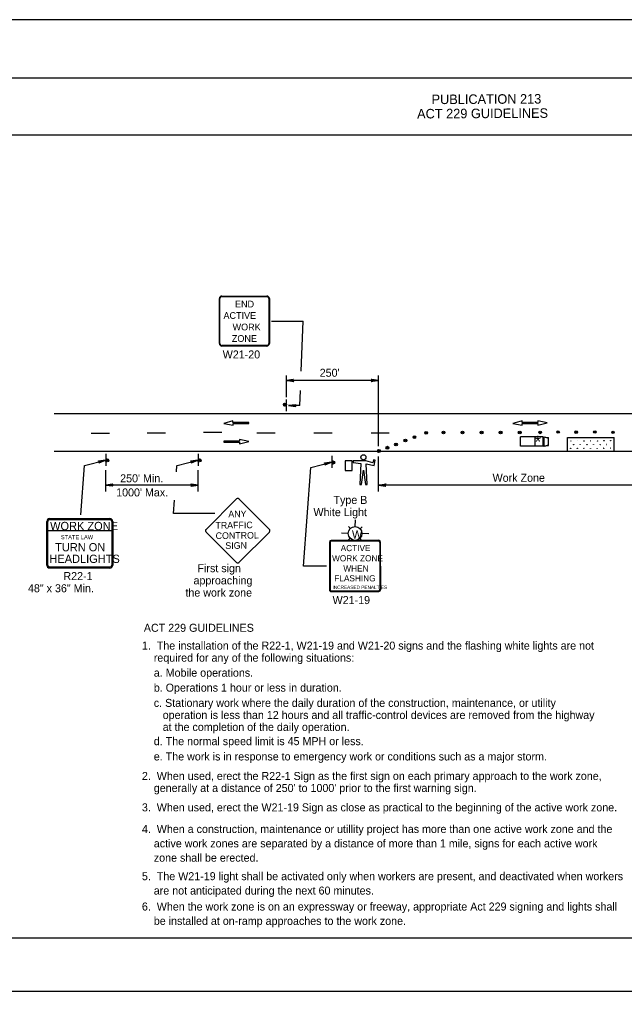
# Model space of a CAD drawing. Extents: x -14145 to -13521, y 30244 to 30661.
# Drawn here: x -13684.79 to -13668.9, y 30559.81 to 30585.31 of the extents above; entities that cross this region are included whole.
import ezdxf

# ---------------------------------------------------------------- set-up
doc = ezdxf.new("R2010")
doc.units = 0
for name, color, linetype in [('1', 7, 'Continuous'), ('10', 7, 'Continuous'), ('2', 7, 'Continuous'), ('4', 7, 'Continuous'), ('61', 7, 'Continuous')]:
    doc.layers.add(name, color=color, linetype=linetype)

msp = doc.modelspace()

# ---------------------------------------------------------------- linework, layer by layer
at = {"layer": '1'}
for p, q in [((-13679.539, 30576.805), (-13679.539, 30577.986)), ((-13679.524, 30576.805), (-13679.524, 30577.986)), ((-13679.473, 30578.052), (-13678.292, 30578.052)), ((-13679.473, 30578.038), (-13678.292, 30578.038)), ((-13678.241, 30577.986), (-13678.241, 30576.805)), ((-13678.226, 30577.986), (-13678.226, 30576.805)), ((-13678.231, 30577.478), (-13678.226, 30577.482)), ((-13678.17, 30577.388), (-13677.338, 30577.388)), ((-13677.389, 30576.084), (-13677.338, 30577.388)), ((-13678.292, 30576.754), (-13679.473, 30576.754)), ((-13678.292, 30576.74), (-13679.473, 30576.74)), ((-13677.778, 30575.4), (-13677.778, 30575.964)), ((-13675.36, 30575.835), (-13677.778, 30575.835)), ((-13675.36, 30574.116), (-13675.36, 30575.964)), ((-13677.424, 30575.178), (-13677.409, 30575.57)), ((-13677.778, 30575.028), (-13677.778, 30575.34)), ((-13677.424, 30575.178), (-13677.724, 30575.178)), ((-13683.877, 30574.968), (-13658.795, 30574.968)), ((-13679.182, 30574.776), (-13679.423, 30574.71)), ((-13679.182, 30574.731), (-13679.182, 30574.776)), ((-13671.596, 30574.775), (-13671.837, 30574.709)), ((-13671.596, 30574.73), (-13671.596, 30574.775)), ((-13670.938, 30574.729), (-13671.182, 30574.775)), ((-13671.182, 30574.775), (-13671.182, 30574.73)), ((-13679.423, 30574.71), (-13679.18, 30574.663)), ((-13678.766, 30574.731), (-13679.182, 30574.731)), ((-13679.18, 30574.663), (-13679.18, 30574.709)), ((-13679.18, 30574.709), (-13678.766, 30574.709)), ((-13678.766, 30574.709), (-13678.766, 30574.731)), ((-13671.837, 30574.709), (-13671.593, 30574.663)), ((-13671.182, 30574.73), (-13671.596, 30574.73)), ((-13671.593, 30574.708), (-13671.179, 30574.708)), ((-13671.593, 30574.663), (-13671.593, 30574.708)), ((-13671.179, 30574.663), (-13670.938, 30574.729)), ((-13671.179, 30574.708), (-13671.179, 30574.663)), ((-13682.425, 30574.446), (-13682.905, 30574.446)), ((-13680.949, 30574.458), (-13681.429, 30574.458)), ((-13679.473, 30574.47), (-13679.953, 30574.47)), ((-13678.766, 30574.239), (-13679.01, 30574.285)), ((-13679.01, 30574.285), (-13679.01, 30574.24)), ((-13678.078, 30574.452), (-13678.558, 30574.452)), ((-13676.578, 30574.452), (-13677.058, 30574.452)), ((-13675.078, 30574.452), (-13675.558, 30574.452)), ((-13671.634, 30574.116), (-13671.634, 30574.362)), ((-13671.04, 30574.362), (-13671.634, 30574.362)), ((-13671.25, 30574.116), (-13671.25, 30574.362)), ((-13671.04, 30574.116), (-13671.04, 30574.362)), ((-13671.04, 30574.362), (-13670.902, 30574.338)), ((-13671.016, 30574.356), (-13670.902, 30574.32)), ((-13671.016, 30574.116), (-13671.016, 30574.356)), ((-13670.902, 30574.128), (-13670.902, 30574.338)), ((-13670.404, 30573.984), (-13670.404, 30574.343)), ((-13670.404, 30574.343), (-13669.18, 30574.343)), ((-13669.18, 30573.984), (-13669.18, 30574.343)), ((-13679.01, 30574.24), (-13679.423, 30574.24)), ((-13679.423, 30574.24), (-13679.423, 30574.218)), ((-13679.423, 30574.218), (-13679.007, 30574.218)), ((-13679.007, 30574.173), (-13678.766, 30574.239)), ((-13679.007, 30574.218), (-13679.007, 30574.173)), ((-13671.04, 30574.116), (-13671.634, 30574.116)), ((-13671.04, 30574.116), (-13670.902, 30574.128)), ((-13671.016, 30574.116), (-13670.902, 30574.146)), ((-13683.877, 30573.984), (-13658.795, 30573.984)), ((-13683.074, 30573.606), (-13682.527, 30573.746)), ((-13682.521, 30573.913), (-13682.521, 30573.601)), ((-13680.65, 30573.606), (-13680.103, 30573.746)), ((-13680.097, 30573.913), (-13680.097, 30573.601)), ((-13676.59, 30573.859), (-13676.59, 30573.547)), ((-13675.495, 30573.755), (-13675.513, 30573.675)), ((-13675.447, 30573.744), (-13675.495, 30573.755)), ((-13675.477, 30573.61), (-13675.447, 30573.744)), ((-13675.358, 30572.922), (-13675.358, 30573.839)), ((-13683.17, 30572.312), (-13683.075, 30573.606)), ((-13682.521, 30572.922), (-13682.521, 30573.484)), ((-13680.663, 30573.441), (-13680.651, 30573.606)), ((-13680.097, 30572.922), (-13680.097, 30573.484)), ((-13677.332, 30570.965), (-13677.142, 30573.552)), ((-13677.141, 30573.552), (-13676.596, 30573.692)), ((-13676.049, 30573.728), (-13676.237, 30573.728)), ((-13676.237, 30573.728), (-13676.237, 30573.478)), ((-13676.049, 30573.478), (-13676.049, 30573.728)), ((-13675.691, 30573.728), (-13676.031, 30573.728)), ((-13676.031, 30573.728), (-13676.031, 30573.683)), ((-13676.031, 30573.683), (-13675.825, 30573.657)), ((-13675.825, 30573.657), (-13675.853, 30573.111)), ((-13675.808, 30573.111), (-13675.754, 30573.485)), ((-13675.754, 30573.485), (-13675.701, 30573.111)), ((-13675.513, 30573.675), (-13675.691, 30573.728)), ((-13675.656, 30573.111), (-13675.682, 30573.647)), ((-13675.682, 30573.647), (-13675.477, 30573.61)), ((-13676.237, 30573.478), (-13676.049, 30573.478)), ((-13680.097, 30573.091), (-13682.521, 30573.091)), ((-13675.853, 30573.111), (-13675.808, 30573.111)), ((-13675.701, 30573.111), (-13675.656, 30573.111)), ((-13667.736, 30573.091), (-13675.358, 30573.091)), ((-13679.09, 30572.73), (-13679.885, 30571.927)), ((-13678.22, 30571.927), (-13679.023, 30572.73)), ((-13680.743, 30572.345), (-13680.717, 30572.7)), ((-13683.993, 30572.214), (-13682.408, 30572.213)), ((-13683.993, 30572.213), (-13682.408, 30572.213)), ((-13679.659, 30572.345), (-13680.743, 30572.345)), ((-13684.067, 30571.89), (-13684.067, 30572.141)), ((-13684.067, 30572.141), (-13684.067, 30572.141)), ((-13684.04, 30570.992), (-13684.04, 30572.141)), ((-13683.993, 30572.187), (-13682.408, 30572.186)), ((-13682.361, 30572.14), (-13682.363, 30570.991)), ((-13682.335, 30572.14), (-13682.336, 30571.889)), ((-13676.15, 30572.005), (-13676.099, 30571.951)), ((-13675.971, 30572.001), (-13675.967, 30572.181)), ((-13675.79, 30571.999), (-13675.844, 30571.946)), ((-13684.067, 30570.991), (-13684.067, 30571.89)), ((-13682.336, 30571.889), (-13684.067, 30571.89)), ((-13682.336, 30571.889), (-13682.336, 30570.99)), ((-13679.885, 30571.86), (-13679.09, 30571.065)), ((-13679.023, 30571.065), (-13678.22, 30571.86)), ((-13676.155, 30571.824), (-13676.334, 30571.829)), ((-13676.156, 30571.645), (-13676.102, 30571.697)), ((-13675.614, 30571.816), (-13675.795, 30571.819)), ((-13676.647, 30571.596), (-13676.646, 30570.345)), ((-13676.63, 30571.582), (-13676.63, 30570.359)), ((-13675.35, 30571.641), (-13676.602, 30571.641)), ((-13675.364, 30571.625), (-13676.59, 30571.624)), ((-13675.796, 30571.639), (-13675.847, 30571.691)), ((-13675.366, 30571.627), (-13675.366, 30571.627)), ((-13675.353, 30571.643), (-13675.353, 30571.643)), ((-13675.322, 30570.359), (-13675.322, 30571.584)), ((-13675.305, 30570.346), (-13675.307, 30571.597)), ((-13682.408, 30570.943), (-13683.993, 30570.945)), ((-13676.726, 30570.965), (-13677.332, 30570.965)), ((-13682.408, 30570.917), (-13683.993, 30570.917)), ((-13676.601, 30570.3), (-13675.349, 30570.3)), ((-13676.589, 30570.317), (-13675.364, 30570.317))]:
    msp.add_line(p, q, dxfattribs=at)
for points in [[(-13677.598, 30575.817), (-13677.604, 30575.829), (-13677.778, 30575.835), (-13677.598, 30575.817), (-13677.592, 30575.805), (-13677.778, 30575.835), (-13677.61, 30575.847), (-13677.604, 30575.859), (-13677.778, 30575.835), (-13677.592, 30575.865), (-13677.604, 30575.859)], [(-13675.54, 30575.859), (-13675.534, 30575.847), (-13675.36, 30575.835), (-13675.54, 30575.859), (-13675.552, 30575.865), (-13675.36, 30575.835), (-13675.534, 30575.829), (-13675.54, 30575.817), (-13675.36, 30575.835), (-13675.552, 30575.805), (-13675.54, 30575.817)], [(-13677.544, 30575.154), (-13677.55, 30575.166), (-13677.724, 30575.178), (-13677.544, 30575.154), (-13677.538, 30575.148), (-13677.724, 30575.178), (-13677.55, 30575.184), (-13677.544, 30575.196), (-13677.724, 30575.178), (-13677.538, 30575.208), (-13677.544, 30575.196)], [(-13682.707, 30573.722), (-13682.695, 30573.71), (-13682.527, 30573.746), (-13682.707, 30573.722), (-13682.713, 30573.728), (-13682.527, 30573.746), (-13682.689, 30573.692), (-13682.695, 30573.68), (-13682.527, 30573.746), (-13682.701, 30573.668), (-13682.695, 30573.68)], [(-13680.283, 30573.722), (-13680.271, 30573.71), (-13680.103, 30573.746), (-13680.283, 30573.722), (-13680.289, 30573.728), (-13680.103, 30573.746), (-13680.265, 30573.692), (-13680.271, 30573.68), (-13680.103, 30573.746), (-13680.277, 30573.668), (-13680.271, 30573.68)], [(-13676.776, 30573.668), (-13676.764, 30573.656), (-13676.596, 30573.692), (-13676.776, 30573.668), (-13676.782, 30573.674), (-13676.596, 30573.692), (-13676.758, 30573.638), (-13676.764, 30573.626), (-13676.596, 30573.692), (-13676.77, 30573.614), (-13676.764, 30573.626)], [(-13682.341, 30573.073), (-13682.347, 30573.085), (-13682.521, 30573.091), (-13682.341, 30573.073), (-13682.335, 30573.061), (-13682.521, 30573.091), (-13682.347, 30573.103), (-13682.341, 30573.115), (-13682.521, 30573.091), (-13682.335, 30573.121), (-13682.341, 30573.115)], [(-13680.277, 30573.115), (-13680.265, 30573.097), (-13680.097, 30573.091), (-13680.277, 30573.115), (-13680.283, 30573.121), (-13680.097, 30573.091), (-13680.265, 30573.079), (-13680.277, 30573.067), (-13680.097, 30573.091), (-13680.283, 30573.061), (-13680.277, 30573.067)], [(-13675.178, 30573.067), (-13675.184, 30573.079), (-13675.358, 30573.091), (-13675.178, 30573.067), (-13675.172, 30573.061), (-13675.358, 30573.091), (-13675.184, 30573.097), (-13675.178, 30573.109), (-13675.358, 30573.091), (-13675.172, 30573.121), (-13675.178, 30573.109)]]:
    msp.add_lwpolyline(points, dxfattribs=at)
for centre, radius in [((-13677.818, 30575.203), 0.0408), ((-13673.656, 30574.473), 0.037), ((-13673.156, 30574.473), 0.037), ((-13672.656, 30574.473), 0.037), ((-13672.156, 30574.473), 0.037), ((-13671.656, 30574.473), 0.037), ((-13671.117, 30574.475), 0.0353), ((-13670.648, 30574.485), 0.0321), ((-13670.175, 30574.482), 0.037), ((-13669.684, 30574.485), 0.0321), ((-13669.206, 30574.477), 0.0327), ((-13674.657, 30574.261), 0.038), ((-13674.658, 30574.258), 0.0155), ((-13674.42, 30574.351), 0.0346), ((-13674.419, 30574.347), 0.0101), ((-13674.109, 30574.461), 0.0354), ((-13674.112, 30574.458), 0.0143), ((-13673.659, 30574.471), 0.0172), ((-13673.159, 30574.471), 0.0172), ((-13672.659, 30574.471), 0.0172), ((-13672.159, 30574.471), 0.0172), ((-13671.659, 30574.471), 0.0172), ((-13671.113, 30574.476), 0.014), ((-13670.647, 30574.483), 0.0143), ((-13670.314, 30574.25), 0.00272), ((-13670.176, 30574.481), 0.0149), ((-13670.139, 30574.253), 0.00272), ((-13669.968, 30574.25), 0.00272), ((-13669.792, 30574.253), 0.00272), ((-13669.683, 30574.483), 0.0143), ((-13669.618, 30574.251), 0.00272), ((-13669.446, 30574.256), 0.00272), ((-13669.444, 30574.254), 0.00272), ((-13669.271, 30574.259), 0.00272), ((-13669.208, 30574.477), 0.00928), ((-13675.349, 30573.986), 0.0379), ((-13675.348, 30573.986), 0.014), ((-13675.13, 30574.073), 0.037), ((-13675.129, 30574.071), 0.0194), ((-13674.902, 30574.16), 0.036), ((-13674.905, 30574.166), 0.0161), ((-13670.319, 30574.055), 0.00272), ((-13670.239, 30574.152), 0.00272), ((-13670.144, 30574.056), 0.00272), ((-13670.068, 30574.152), 0.00272), ((-13669.971, 30574.056), 0.00272), ((-13669.891, 30574.153), 0.00272), ((-13669.797, 30574.057), 0.00272), ((-13669.718, 30574.153), 0.00272), ((-13669.624, 30574.058), 0.00272), ((-13669.543, 30574.154), 0.00272), ((-13669.451, 30574.061), 0.00272), ((-13669.45, 30574.058), 0.00272), ((-13669.372, 30574.158), 0.00272), ((-13669.277, 30574.062), 0.00272), ((-13682.483, 30573.74), 0.0408), ((-13680.059, 30573.74), 0.0408), ((-13675.759, 30573.822), 0.0672), ((-13676.55, 30573.686), 0.0408), ((-13675.976, 30571.823), 0.18)]:
    msp.add_circle(centre, radius, dxfattribs=at)
for centre, radius, start, end in [((-13679.473, 30577.986), 0.0656, 90, 180), ((-13679.473, 30577.986), 0.0514, 90, 180), ((-13678.292, 30577.986), 0.0656, 0, 90), ((-13678.292, 30577.986), 0.0514, 0, 90), ((-13679.473, 30576.805), 0.0656, 180, 270), ((-13679.473, 30576.805), 0.0514, 180, 270), ((-13678.292, 30576.805), 0.0656, 270, 0), ((-13678.292, 30576.805), 0.0514, 270, 0), ((-13677.813, 30575.195), 0.0214, 9.521, 4.2501), ((-13682.488, 30573.748), 0.0214, 189.521, 184.2501), ((-13680.064, 30573.748), 0.0214, 189.521, 184.2501), ((-13676.555, 30573.694), 0.0214, 189.521, 184.2501), ((-13679.055, 30572.696), 0.0465, 45, 135), ((-13683.994, 30572.14), 0.0732, 89.9817, 179.9817), ((-13682.409, 30572.14), 0.0732, 359.9817, 89.9817), ((-13683.994, 30572.14), 0.0464, 89.9817, 179.9817), ((-13682.409, 30572.14), 0.0464, 359.9817, 89.9817), ((-13679.855, 30571.897), 0.0465, 135, 225), ((-13678.256, 30571.897), 0.0465, 315, 45), ((-13676.605, 30571.598), 0.0447, 90.038, 180.038), ((-13676.592, 30571.585), 0.041, 90.038, 180.038), ((-13675.366, 30571.586), 0.041, 0.038, 90.038), ((-13675.353, 30571.599), 0.0447, 0.038, 90.038), ((-13683.994, 30570.991), 0.0732, 179.9817, 269.9817), ((-13683.994, 30570.991), 0.0464, 179.9817, 269.9817), ((-13682.409, 30570.99), 0.0464, 269.9817, 359.9817), ((-13682.409, 30570.99), 0.0732, 269.9817, 359.9817), ((-13679.055, 30571.098), 0.0465, 225, 315), ((-13676.604, 30570.346), 0.0447, 180.038, 270.038), ((-13676.591, 30570.359), 0.041, 180.038, 270.038), ((-13675.365, 30570.36), 0.041, 270.038, 0.038), ((-13675.352, 30570.347), 0.0447, 270.038, 0.038)]:
    msp.add_arc(centre, radius, start, end, dxfattribs=at)
at = {"layer": '10'}
for p, q in [((-13687.874, 30583.777), (-13656.422, 30583.777)), ((-13687.874, 30582.277), (-13656.422, 30582.277)), ((-13656.422, 30561.207), (-13687.874, 30561.207))]:
    msp.add_line(p, q, dxfattribs=at)
at = {"layer": '61'}
msp.add_lwpolyline([(-13688.174, 30585.307), (-13655.174, 30585.307), (-13655.174, 30559.807), (-13688.174, 30559.807)], close=True, dxfattribs=at)

# ---------------------------------------------------------------- texts
at = {"layer": '1'}
for s, p in [('END', (-13679.127, 30577.752)), ('ACTIVE', (-13679.43, 30577.452)), ('WORK', (-13679.191, 30577.15)), ('ZONE', (-13679.21, 30576.849))]:
    msp.add_text(s, height=0.1771, dxfattribs=at).set_placement(p)
for s, height, rotation, p in [('*', 0.318, 0.7185, (-13671.258, 30574.07)), ('ANY', 0.1735, 0.7566, (-13679.302, 30572.246)), ('WORK ZONE', 0.216, 359.9817, (-13683.98, 30571.911)), ('TRAFFIC', 0.1733, 0.7588, (-13679.64, 30571.949)), ('STATE LAW', 0.108, 359.9817, (-13683.696, 30571.673)), ('CONTROL', 0.1733, 0.7588, (-13679.635, 30571.677)), ('W', 0.216, 0.0454, (-13676.06, 30571.69)), ('TURN ON', 0.216, 359.9817, (-13683.848, 30571.355)), ('SIGN', 0.1733, 0.7588, (-13679.38, 30571.417)), ('ACTIVE', 0.162, 0.038, (-13676.354, 30571.359)), ('HEADLIGHTS', 0.216, 359.9817, (-13683.998, 30571.051)), ('WORK ZONE', 0.162, 0.038, (-13676.581, 30571.091)), ('WHEN', 0.162, 0.038, (-13676.285, 30570.825)), ('FLASHING', 0.162, 0.038, (-13676.522, 30570.566)), ('INCREASED PENALTIES', 0.08939, 0.038, (-13676.57, 30570.366))]:
    msp.add_text(s, height=height, rotation=rotation, dxfattribs=at).set_placement(p)
at = {"layer": '2'}
for s, p in [('W21-20', (-13679.451, 30576.414)), ("250'", (-13676.905, 30575.934)), ("250' Min.", (-13682.142, 30573.165)), ('Work Zone', (-13672.368, 30573.179)), ("1000' Max.", (-13682.247, 30572.795)), ('Type B', (-13676.543, 30572.598)), ('White Light', (-13677.069, 30572.278)), ('First sign', (-13680.112, 30570.807)), ('R22-1', (-13683.631, 30570.601)), ('approaching', (-13680.217, 30570.487)), ('48" x 36" Min.', (-13684.561, 30570.281)), ('the work zone', (-13680.429, 30570.167)), ('W21-19', (-13676.567, 30569.971)), ('ACT 229 GUIDELINES', (-13681.52, 30569.244)), ('1.  The installation of the R22-1, W21-19 and W21-20 signs and the flashing white lights are not', (-13681.571, 30568.777)), ('    required for any of the following situations:', (-13681.571, 30568.46)), ('    a. Mobile operations.', (-13681.571, 30568.066)), ('    b. Operations 1 hour or less in duration.', (-13681.571, 30567.674)), ('    c. Stationary work where the daily duration of the construction, maintenance, or utility', (-13681.571, 30567.274)), ('       operation is less than 12 hours and all traffic-control devices are removed from the highway', (-13681.571, 30566.957)), ('       at the completion of the daily operation.', (-13681.571, 30566.642)), ('    d. The normal speed limit is 45 MPH or less.', (-13681.571, 30566.27)), ('    e. The work is in response to emergency work or conditions such as a major storm.', (-13681.571, 30565.869)), ('2.  When used, erect the R22-1 Sign as the first sign on each primary approach to the work zone,', (-13681.571, 30565.357)), ("    generally at a distance of 250' to 1000' prior to the first warning sign.", (-13681.571, 30565.042)), ('3.  When used, erect the W21-19 Sign as close as practical to the beginning of the active work zone.', (-13681.571, 30564.533)), ('4.  When a construction, maintenance or utillity project has more than one active work zone and the', (-13681.571, 30563.966)), ('    active work zones are separated by a distance of more than 1 mile, signs for each active work', (-13681.571, 30563.589)), ('    zone shall be erected.', (-13681.571, 30563.213)), ('5.  The W21-19 light shall be activated only when workers are present, and deactivated when workers', (-13681.571, 30562.728)), ('    are not anticipated during the next 60 minutes.', (-13681.571, 30562.351)), ('6.  When the work zone is on an expressway or freeway, appropriate Act 229 signing and lights shall', (-13681.571, 30561.932)), ('    be installed at on-ramp approaches to the work zone.', (-13681.571, 30561.555))]:
    msp.add_text(s, height=0.21, dxfattribs=at).set_placement(p)
at = {"layer": '4'}
for s, p in [('PUBLICATION 213', (-13673.969, 30583.085)), ('ACT 229 GUIDELINES', (-13674.348, 30582.708))]:
    msp.add_text(s, height=0.25, rotation=0.31, dxfattribs=at).set_placement(p)

doc.saveas('drawing.dxf')
